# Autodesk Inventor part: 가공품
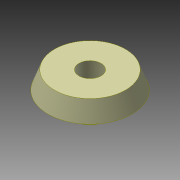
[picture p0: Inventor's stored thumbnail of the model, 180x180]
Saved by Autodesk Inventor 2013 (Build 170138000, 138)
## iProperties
Created: 2023-11
Part Number: 가공품
Material: 알루미늄 6061
Document SubType Name: Modeling
Designer: mdu-01
Density: 1 g/cm^3
Author: mdu-01
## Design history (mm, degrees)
sketch "스케치1"
  geometry: L1 (0, 4)-(0, -4); L2 (0, 4)-(8.044, 4); L3 (8.044, 4)-(9.5, 0); L4 (9.5, 0)-(5, 0); L5 (5, 0)-(5, -3); L6 (4, -4)-(0, -4); L7 (5, -3)-(4, -4); 2 further points
  constraints: 14 end point, 3 point on line, 2 parallel, 2 perpendicular, 1 midpoint, 1 vertical
  dimensions: "d0" = 4 distance between parallel lines of L6 L4; "d3" = 1 distance of L5.end point (5, -4); "d4" = 1 distance of L6.start point (5, -4) (= d3); "d5" = 10 diameter of L5 L1; "d6" = 19 diameter of L3.end L1; "d7" = 8 distance between parallel lines of L6 L2; "d8" = 20 deg angle of L1 L3
revolve "회전1" sketch "스케치1" stored, may be unused: angle "d9" = 90 deg
hole "구멍1" diameter "d12" = 5; stored, may be unused: countersink angle "d16" = 90 deg, drill point angle "d18" = 118 deg; dims "d10" = 10, "d11" = 10, "d13" = 6, "d14" = 4, "d15" = 2, "d17" = 5
node "솔리드1"
